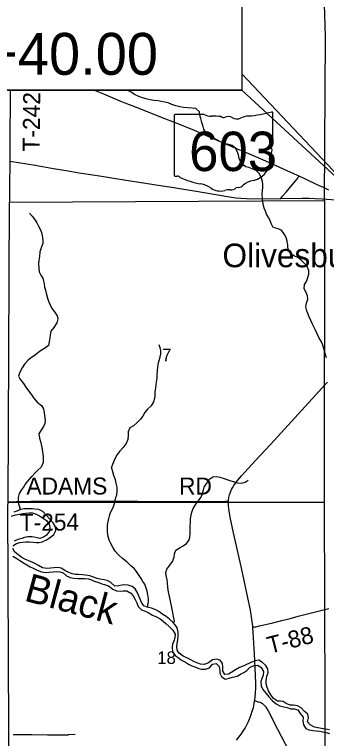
# Model space of a CAD drawing. Extents: x 0 to 34, y 0 to 22.
# Drawn here: x 5.455 to 6.497, y 15.494 to 17.915 of the extents above; entities that cross this region are included whole.
import ezdxf

# ---------------------------------------------------------------- set-up
doc = ezdxf.new("R2010")
doc.units = 0
for name, color, linetype in [('Default', 7, 'Continuous'), ('GM_X_County_Road', 7, 'Continuous'), ('GM_X_Major_River', 7, 'Continuous'), ('GM_X_Major_River_Text', 7, 'Continuous'), ('GM_X_Minor_River', 7, 'Continuous'), ('GM_X_Section', 7, 'Continuous'), ('GM_X_Section_Text', 7, 'Continuous'), ('GM_X_State_Location', 7, 'Continuous'), ('GM_X_State_Route', 7, 'Continuous'), ('GM_X_State_Shield', 7, 'Continuous'), ('GM_X_Township_Road', 7, 'Continuous'), ('GM_X_Township_Road_Text', 7, 'Continuous'), ('GM_X_Unincorporated_Text', 7, 'Continuous')]:
    doc.layers.add(name, color=color, linetype=linetype)

msp = doc.modelspace()

# ---------------------------------------------------------------- linework, layer by layer
at = {"layer": 'Default'}
for points in [[(4.3145, 18.3355), (4.3121, 18.3355), (4.3121, 17.6612), (6.2145, 17.6612), (6.2145, 17.662), (4.3145, 17.662)], [(6.2148, 17.662), (6.6166, 17.2903), (6.2148, 17.7158)]]:
    msp.add_lwpolyline(points, close=True, dxfattribs=at)
msp.add_lwpolyline([(6.2148, 18.2783), (6.2148, 17.662), (4.3145, 17.662), (4.3145, 18.28)], dxfattribs=at)
at = {"layer": 'GM_X_County_Road'}
msp.add_lwpolyline([(6.3846, 15.4277), (6.3348, 15.5244), (6.3034, 15.5851), (6.299, 15.5934), (6.2956, 15.5987), (6.2936, 15.6012), (6.2915, 15.6035), (6.2892, 15.6057), (6.2868, 15.6078), (6.2842, 15.6096), (6.2814, 15.6112), (6.2786, 15.6126), (6.2757, 15.6138), (6.2697, 15.6158), (6.2637, 15.6176), (6.2574, 15.6194)], dxfattribs=at)
at = {"layer": 'GM_X_Major_River'}
for points in [[(5.4447, 16.2375), (5.4588, 16.2412), (5.472, 16.2443), (5.4834, 16.2458), (5.4929, 16.2473), (5.5039, 16.2485), (5.5141, 16.2481), (5.5278, 16.2439), (5.5387, 16.2386), (5.549, 16.2322), (5.5622, 16.223), (5.571, 16.2105), (5.5736, 16.1995), (5.5717, 16.1866), (5.5618, 16.1737), (5.552, 16.1673), (5.5398, 16.1624), (5.5266, 16.1654), (5.5133, 16.168), (5.5, 16.1677), (5.489, 16.1654), (5.4796, 16.1631), (5.4663, 16.1589), (5.4542, 16.1536)], [(5.4496, 16.1385), (5.4617, 16.1457), (5.4731, 16.1491), (5.483, 16.1506), (5.4925, 16.151), (5.5053, 16.151), (5.5179, 16.1498), (5.5277, 16.1487), (5.5372, 16.1487), (5.5474, 16.1514), (5.5615, 16.1578), (5.5747, 16.1654), (5.5869, 16.176), (5.5937, 16.1893), (5.5922, 16.2014), (5.5842, 16.2151), (5.5736, 16.2268), (5.5619, 16.2394), (5.5497, 16.2526), (5.5361, 16.2598), (5.5232, 16.2606), (5.5137, 16.2614), (5.5005, 16.2621), (5.4857, 16.2617), (5.4758, 16.2591), (5.4626, 16.2541), (5.4527, 16.2503)], [(6.0438, 15.7566), (6.0332, 15.7626), (6.0181, 15.7695), (6.0048, 15.7789), (5.998, 15.7896), (5.9969, 15.8009), (5.998, 15.8112), (6.0003, 15.8237), (6.0022, 15.8362), (6.0022, 15.8495), (5.9984, 15.8635), (5.9923, 15.8734), (5.9836, 15.8832), (5.9734, 15.8927), (5.9616, 15.9014), (5.951, 15.9086), (5.937, 15.9185), (5.9272, 15.9238), (5.9124, 15.9295), (5.8984, 15.9333), (5.8877, 15.9371), (5.8794, 15.9481), (5.8749, 15.9598), (5.8696, 15.9727), (5.865, 15.9826), (5.8582, 15.9947), (5.848, 16.0019), (5.8343, 16.0069), (5.8237, 16.0073), (5.8139, 16.0061), (5.804, 16.0038), (5.7907, 16.0035), (5.7771, 16.0152), (5.7642, 16.0217), (5.7547, 16.0239), (5.7403, 16.027), (5.7308, 16.0292), (5.7161, 16.0342), (5.7062, 16.0372), (5.6918, 16.0399), (5.6823, 16.041), (5.6687, 16.0421), (5.6588, 16.0425), (5.6482, 16.0444), (5.6368, 16.049), (5.6236, 16.0558), (5.6107, 16.063), (5.6001, 16.0653), (5.5864, 16.0649), (5.5751, 16.0634), (5.5629, 16.0618), (5.5485, 16.0649), (5.5349, 16.0721), (5.5254, 16.0774), (5.5159, 16.0823), (5.5027, 16.088), (5.4898, 16.0933), (5.4792, 16.099), (5.4663, 16.1089), (5.4564, 16.1165), (5.4496, 16.1286)], [(5.4496, 16.1032), (5.4629, 16.0952), (5.4727, 16.0891), (5.4822, 16.0831), (5.4958, 16.074), (5.5076, 16.0679), (5.5174, 16.0634), (5.5311, 16.0569), (5.5455, 16.0508), (5.5587, 16.0486), (5.5713, 16.0497), (5.5841, 16.0516), (5.5963, 16.052), (5.6061, 16.0512), (5.6175, 16.0478), (5.6289, 16.0376), (5.641, 16.0319), (5.6535, 16.0296), (5.6664, 16.0289), (5.6804, 16.0289), (5.6899, 16.0292), (5.7028, 16.0273), (5.7123, 16.0239), (5.7217, 16.0198), (5.7335, 16.016), (5.7464, 16.011), (5.7562, 16.0084), (5.7695, 16.0042), (5.7831, 15.9928), (5.796, 15.9871), (5.8085, 15.9868), (5.818, 15.9879), (5.8305, 15.9875), (5.8438, 15.9803), (5.8517, 15.9708), (5.8582, 15.9587), (5.8635, 15.9473), (5.8684, 15.9348), (5.8798, 15.9242), (5.8919, 15.9193), (5.9018, 15.9151), (5.9158, 15.9067), (5.929, 15.9003), (5.9412, 15.8942), (5.9514, 15.8866), (5.9609, 15.8783), (5.9719, 15.8688), (5.984, 15.8555), (5.9916, 15.843), (5.9912, 15.8301), (5.987, 15.8195), (5.9832, 15.8089), (5.9813, 15.7994), (5.9824, 15.7839), (5.9919, 15.771), (6.0014, 15.7645), (6.0131, 15.7558), (6.026, 15.7486), (6.0359, 15.7429)], [(6.0359, 15.7429), (6.0457, 15.7383), (6.0579, 15.7338), (6.0704, 15.7277), (6.0802, 15.7251), (6.0935, 15.7255), (6.106, 15.7304), (6.1166, 15.7418), (6.1288, 15.7448), (6.139, 15.7349), (6.1409, 15.7217), (6.1416, 15.7122), (6.1466, 15.7012), (6.1587, 15.6921), (6.1727, 15.6959), (6.1837, 15.6985), (6.1985, 15.7019), (6.2106, 15.7088), (6.2209, 15.7145), (6.2311, 15.7213), (6.2429, 15.7327), (6.2554, 15.7384), (6.2683, 15.7395), (6.2793, 15.7315), (6.2868, 15.7175), (6.2857, 15.7039), (6.2815, 15.694), (6.2785, 15.683), (6.2792, 15.6701), (6.2849, 15.6572), (6.2959, 15.6443), (6.305, 15.6329), (6.316, 15.6212), (6.3292, 15.6102), (6.3414, 15.603), (6.3546, 15.5992), (6.3664, 15.5973), (6.3778, 15.5935), (6.3899, 15.5935), (6.402, 15.5897), (6.4092, 15.5779), (6.4191, 15.5647), (6.4187, 15.5521), (6.4206, 15.54), (6.4285, 15.5275), (6.438, 15.5229), (6.4513, 15.5207), (6.4634, 15.5199), (6.4736, 15.5184), (6.485, 15.5157), (6.4968, 15.5135), (6.507, 15.5108)], [(6.5074, 15.5229), (6.4937, 15.5252), (6.4812, 15.5275), (6.468, 15.5294), (6.4577, 15.532), (6.4433, 15.5392), (6.4342, 15.5499), (6.4376, 15.5628), (6.435, 15.5753), (6.4232, 15.5855), (6.413, 15.5965), (6.4001, 15.6033), (6.3876, 15.6056), (6.3755, 15.6056), (6.3622, 15.6106), (6.3528, 15.617), (6.3433, 15.6185), (6.3338, 15.6185), (6.3209, 15.6276), (6.3118, 15.6401), (6.3035, 15.6534), (6.2989, 15.664), (6.2963, 15.6765), (6.2963, 15.6864), (6.2986, 15.702), (6.302, 15.7133), (6.3016, 15.7266), (6.2933, 15.7391), (6.2838, 15.7475), (6.2717, 15.7558), (6.2588, 15.7532), (6.2467, 15.749), (6.2209, 15.7368), (6.2072, 15.7315), (6.1936, 15.7239), (6.1811, 15.7156), (6.1701, 15.7084), (6.1579, 15.7076), (6.1511, 15.7186), (6.1507, 15.733), (6.1496, 15.7444), (6.1424, 15.7562), (6.1295, 15.7588), (6.1163, 15.7566), (6.103, 15.7467), (6.0886, 15.741), (6.0768, 15.7425), (6.0643, 15.7471), (6.0541, 15.7516), (6.0438, 15.7566)]]:
    msp.add_lwpolyline(points, dxfattribs=at)
at = {"layer": 'GM_X_Minor_River'}
for points in [[(6.0807, 17.554), (6.0777, 17.5665), (6.0747, 17.5783), (6.0729, 17.5893), (6.0612, 17.6), (6.0483, 17.602), (6.0327, 17.6024), (6.0202, 17.604), (6.0073, 17.606), (5.9945, 17.6091), (5.9804, 17.6141), (5.9679, 17.6195), (5.9569, 17.6218), (5.9456, 17.6237), (5.935, 17.6257), (5.9221, 17.6273), (5.9088, 17.6296), (5.8982, 17.632), (5.8823, 17.6366), (5.8705, 17.6404), (5.8565, 17.647), (5.8467, 17.6535), (5.8361, 17.6592), (5.8273, 17.662)], [(6.4978, 16.7666), (6.4925, 16.781), (6.4895, 16.7932), (6.4851, 16.8088), (6.4802, 16.8202), (6.4723, 16.835), (6.4663, 16.8472), (6.461, 16.8594), (6.4554, 16.87), (6.4497, 16.8814), (6.4452, 16.8913), (6.4396, 16.9043), (6.4351, 16.9145), (6.4321, 16.924), (6.4288, 16.9373), (6.4307, 16.9491), (6.4346, 16.9631), (6.4335, 16.9741), (6.4294, 16.9852), (6.4233, 16.997), (6.4242, 17.0121), (6.4311, 17.022), (6.4341, 17.0322), (6.438, 17.047), (6.4384, 17.0591), (6.4324, 17.0717), (6.4222, 17.0843), (6.4128, 17.0938), (6.4015, 17.1022), (6.3901, 17.1065), (6.3791, 17.113), (6.372, 17.1248), (6.3686, 17.1343), (6.3679, 17.1438), (6.3661, 17.1567), (6.3627, 17.1688), (6.3571, 17.1795), (6.3469, 17.1936), (6.3325, 17.1997), (6.3192, 17.2028), (6.3125, 17.2158), (6.3087, 17.2264), (6.3034, 17.2359), (6.297, 17.247), (6.2937, 17.2572), (6.2896, 17.2675), (6.2869, 17.2774), (6.2847, 17.2888), (6.2832, 17.2987), (6.2829, 17.3139), (6.2838, 17.3264), (6.2842, 17.3359), (6.2842, 17.3461), (6.2831, 17.3568), (6.2794, 17.3712), (6.2726, 17.383), (6.2621, 17.3929), (6.2492, 17.3987), (6.2375, 17.4033), (6.228, 17.4056), (6.2129, 17.4159), (6.2061, 17.4331), (6.2031, 17.4452), (6.199, 17.4566), (6.1941, 17.4665), (6.1828, 17.4772), (6.1707, 17.4799), (6.16, 17.4819), (6.1434, 17.4892), (6.1328, 17.4941), (6.1203, 17.5014), (6.1059, 17.5091), (6.0953, 17.5182), (6.0874, 17.5312), (6.0852, 17.5407), (6.0807, 17.554)], [(5.5051, 17.2509), (5.5146, 17.2402), (5.5214, 17.2307), (5.5297, 17.2185), (5.5349, 17.2074), (5.5409, 17.1968), (5.5451, 17.1861), (5.5473, 17.1763), (5.5495, 17.1588), (5.5494, 17.1493), (5.5448, 17.1379), (5.5394, 17.1216), (5.5382, 17.1057), (5.5363, 17.092), (5.5355, 17.0818), (5.5358, 17.067), (5.5376, 17.0548), (5.5425, 17.0434), (5.5496, 17.0335), (5.5522, 17.0233), (5.5541, 17.0138), (5.5556, 17.0035), (5.5582, 16.9932), (5.5608, 16.9826), (5.5649, 16.9663), (5.5682, 16.9564), (5.5739, 16.9438), (5.5799, 16.9313), (5.5882, 16.9202), (5.5976, 16.9069), (5.5994, 16.897), (5.5967, 16.8837), (5.5864, 16.8686), (5.5765, 16.8557), (5.5741, 16.8428), (5.5726, 16.833), (5.5714, 16.8197), (5.5687, 16.8079), (5.5553, 16.7978), (5.5424, 16.7906), (5.531, 16.7816), (5.5207, 16.7736), (5.5089, 16.7653), (5.4994, 16.7582), (5.4883, 16.7457), (5.4807, 16.7328), (5.4734, 16.7188), (5.4684, 16.7059), (5.4733, 16.6961), (5.4853, 16.6812), (5.4933, 16.669), (5.5023, 16.6564), (5.5129, 16.642), (5.5189, 16.6324), (5.531, 16.6187), (5.5453, 16.6069), (5.5517, 16.5958), (5.5543, 16.5829), (5.5572, 16.5571), (5.5568, 16.5472), (5.5514, 16.5366), (5.5457, 16.5268), (5.5365, 16.5124), (5.5387, 16.4976), (5.5417, 16.4866), (5.5439, 16.4771), (5.5465, 16.4664), (5.5491, 16.4524), (5.551, 16.4372), (5.5513, 16.4265), (5.5505, 16.4171), (5.5438, 16.4013)], [(5.9375, 16.8115), (5.9401, 16.8016), (5.9423, 16.7913), (5.943, 16.7799), (5.9411, 16.7697), (5.938, 16.7602), (5.9346, 16.7504), (5.9326, 16.7363), (5.9318, 16.723), (5.9306, 16.7105), (5.9301, 16.6984), (5.9286, 16.6855), (5.9274, 16.676), (5.9258, 16.6654), (5.9242, 16.6529), (5.9238, 16.6411), (5.9226, 16.6312), (5.9195, 16.6191), (5.9119, 16.6062), (5.8997, 16.5953), (5.8905, 16.5843), (5.8836, 16.5718), (5.876, 16.5612), (5.8622, 16.548), (5.8527, 16.5397), (5.8405, 16.5326), (5.8352, 16.5197), (5.8347, 16.5079), (5.8335, 16.4939), (5.8282, 16.4802), (5.8186, 16.467), (5.8056, 16.4534), (5.798, 16.4432), (5.7923, 16.4333), (5.7869, 16.4216), (5.7827, 16.4102), (5.7796, 16.4008)], [(5.4742, 16.2585), (5.4736, 16.2644), (5.4698, 16.2773), (5.4679, 16.2871), (5.4679, 16.2993), (5.4721, 16.3133), (5.4781, 16.3239), (5.4846, 16.3334), (5.4907, 16.3433), (5.4994, 16.3547), (5.5127, 16.3702), (5.5225, 16.3812), (5.5324, 16.3899), (5.5438, 16.4013)], [(5.9006, 15.9327), (5.901, 15.9409), (5.9022, 15.9511), (5.9022, 15.9606), (5.9003, 15.9746), (5.8984, 15.9868), (5.8942, 16.0001), (5.8904, 16.0095), (5.884, 16.019), (5.8783, 16.0289), (5.8715, 16.0387), (5.8624, 16.052), (5.8544, 16.0619), (5.845, 16.0706), (5.831, 16.0835), (5.8154, 16.0956), (5.8029, 16.1074), (5.7912, 16.1207), (5.7843, 16.1309), (5.7768, 16.1457), (5.7711, 16.1575), (5.7677, 16.1696), (5.7658, 16.1832), (5.7654, 16.195), (5.7662, 16.2071), (5.7685, 16.2197), (5.77, 16.2291), (5.7723, 16.2386), (5.7757, 16.25), (5.781, 16.2595), (5.7863, 16.2701), (5.7894, 16.2796), (5.7916, 16.2898), (5.7939, 16.2993), (5.7966, 16.3088), (5.7981, 16.3209), (5.7977, 16.3346), (5.7947, 16.3475), (5.792, 16.3585), (5.7871, 16.3729), (5.7841, 16.3858), (5.7796, 16.4008)], [(5.9865, 15.88), (5.9893, 15.8863), (5.9867, 15.9022), (5.9844, 15.9147), (5.9821, 15.9257), (5.9791, 15.9371), (5.9772, 15.9477), (5.9749, 15.9591), (5.9727, 15.969), (5.9708, 15.9788), (5.9685, 15.9898), (5.9674, 15.9993), (5.9663, 16.0137), (5.9647, 16.0243), (5.9613, 16.0384), (5.961, 16.0486), (5.9636, 16.06), (5.9742, 16.0736), (5.9826, 16.0858), (5.9883, 16.0998), (5.9898, 16.1112), (5.9944, 16.1237), (6.008, 16.1321), (6.019, 16.1378), (6.0296, 16.1453), (6.0376, 16.1556), (6.0406, 16.1658), (6.0414, 16.1818), (6.0414, 16.195), (6.0422, 16.2056), (6.0426, 16.2151), (6.0429, 16.2261), (6.0437, 16.2356), (6.0475, 16.2504), (6.0521, 16.2633), (6.0604, 16.2773), (6.071, 16.291), (6.0782, 16.3005), (6.0832, 16.3126), (6.0862, 16.3248), (6.0885, 16.3346), (6.0976, 16.3475), (6.1044, 16.36), (6.1181, 16.3688), (6.131, 16.3695), (6.1408, 16.3672), (6.1552, 16.3631), (6.1647, 16.3597), (6.175, 16.3566), (6.189, 16.3525), (6.1992, 16.3487), (6.2121, 16.3471), (6.2257, 16.3506), (6.2352, 16.3574)]]:
    msp.add_lwpolyline(points, dxfattribs=at)
at = {"layer": 'GM_X_Section'}
for points in [[(5.4402, 17.662), (5.4379, 17.2873), (6.4911, 17.2929), (6.4945, 17.8409), (6.4805, 18.2714), (6.2148, 18.2748), (6.2148, 17.662)], [(5.4379, 17.2873), (6.4911, 17.2929), (6.4897, 16.2833), (5.4343, 16.2844)], [(5.4343, 16.2844), (6.4897, 16.2833), (6.4927, 15.2726), (5.4377, 15.2688), (5.4328, 16.2708)]]:
    msp.add_lwpolyline(points, close=True, dxfattribs=at)
at = {"layer": 'GM_X_State_Route'}
for points in [[(6.2082, 17.4615), (6.1586, 17.4824), (6.1045, 17.506), (6.056, 17.5267), (5.9986, 17.5504), (5.9465, 17.5708), (5.8712, 17.6), (5.8164, 17.6219), (5.7533, 17.6481), (5.7201, 17.662)], [(6.5049, 17.3275), (6.4937, 17.3328), (6.4848, 17.337), (6.4763, 17.3412), (6.4596, 17.3487), (6.406, 17.3741), (6.4006, 17.3766), (6.3411, 17.4033), (6.2844, 17.4288), (6.2302, 17.4522), (6.2082, 17.4615)], [(5.4404, 17.4242), (5.5242, 17.4104), (5.5855, 17.4001), (5.6346, 17.3919), (5.6714, 17.3858), (5.7389, 17.3751), (5.828, 17.3611), (5.8924, 17.3511), (5.9354, 17.3443), (5.9875, 17.3361), (6.0886, 17.319), (6.1805, 17.3036), (6.1959, 17.3016), (6.2113, 17.3002), (6.2299, 17.2993), (6.2546, 17.2989), (6.3446, 17.299), (6.4161, 17.3004), (6.4379, 17.3003), (6.4597, 17.2995), (6.4845, 17.2979), (6.5433, 17.2935)], [(6.2144, 16.0585), (6.209, 16.083), (6.1895, 16.171), (6.1768, 16.2286), (6.1732, 16.247), (6.1708, 16.2624), (6.1698, 16.2717), (6.1696, 16.2811), (6.1699, 16.2869), (6.1701, 16.2905), (6.1714, 16.2998), (6.1736, 16.3089), (6.1765, 16.3179), (6.1801, 16.3266), (6.1829, 16.3322), (6.1876, 16.3403), (6.193, 16.348), (6.2008, 16.3578), (6.2132, 16.3718), (6.2596, 16.422), (6.31, 16.4769), (6.4153, 16.5912), (6.4608, 16.6422), (6.4814, 16.6655), (6.492, 16.6769), (6.5008, 16.6856)], [(6.1969, 15.4884), (6.2047, 15.498), (6.2121, 15.5079), (6.219, 15.5182), (6.2254, 15.5288), (6.2313, 15.5397), (6.2366, 15.5508), (6.2414, 15.5622), (6.2457, 15.5738), (6.2496, 15.5856), (6.253, 15.5975), (6.2557, 15.6096), (6.2574, 15.6194), (6.2578, 15.6218), (6.2594, 15.6341), (6.2605, 15.6464), (6.2612, 15.6619), (6.2612, 15.6774), (6.2602, 15.7053), (6.2565, 15.7767), (6.2527, 15.8481), (6.2514, 15.8646), (6.2509, 15.8698), (6.2485, 15.8914), (6.2459, 15.9098), (6.2426, 15.9281), (6.2351, 15.9646), (6.2144, 16.0585)]]:
    msp.add_lwpolyline(points, dxfattribs=at)
at = {"layer": 'GM_X_State_Shield'}
for p, q in [((5.9889, 17.5772), (5.9889, 17.3771)), ((6.0887, 17.5806), (5.9921, 17.5806)), ((6.3185, 17.4809), (6.3185, 17.5856)), ((6.3185, 17.4809), (6.3185, 17.4809))]:
    msp.add_line(p, q, dxfattribs=at)
for centre, major_axis, start_param, end_param in [((5.9927, 17.5776), (0.00382, 0), 1.712693, 3.28349), ((6.1117, 17.6039), (0.037, 0), 4.042523, 4.731795), ((6.2011, 17.8535), (0.3495, 0), 4.814394, 5.042369), ((6.3148, 17.586), (0.00367, 0), 6.141152, 7.989035), ((6.1239, 17.4683), (0.133, 0), 1.404758, 1.657858), ((6.1541, 17.5786), (0.0107, 0), 3.836095, 5.185415), ((6.1698, 17.5555), (0.0222, 0), 0.950623, 2.079405), ((6.1985, 17.5872), (0.0267, 0), 4.081561, 5.145723), ((6.2457, 17.5195), (0.0703, 0), 1.699011, 2.107814), ((6.3146, 17.4805), (0.00393, 0), 5.05454, 6.418171), ((6.3176, 17.4732), (0.00568, 0), 1.883978, 3.671073), ((6.2815, 17.46), (0.0341, 0), 5.934695, 6.695948), ((6.2207, 17.4238), (0.0874, 0), 5.101752, 6.440018), ((6.3316, 17.4371), (0.0248, 0), 2.387724, 3.262537), ((5.9927, 17.3766), (0.00385, 0), 3.00124, 4.508301), ((5.9933, 17.3971), (0.0294, 0), 4.665946, 4.897461), ((5.9993, 17.3655), (0.0106, 0), 0.519207, 1.627899), ((6.1331, 17.5453), (0.2524, 0), 4.195997, 4.488961), ((6.0579, 17.2872), (0.079, 0), 0.823519, 1.323587), ((6.2001, 17.3302), (0.00752, 0), 1.147584, 2.315152), ((6.1969, 17.3577), (0.0282, 0), 4.937069, 5.64225), ((6.2575, 17.3209), (0.0479, 0), 1.647645, 2.488434), ((6.1433, 17.3645), (0.0501, 0), 4.026481, 4.996735), ((6.1723, 17.2953), (0.0412, 0), 1.495662, 1.94098), ((6.1759, 17.3495), (0.0267, 0), 4.691044, 5.507374)]:
    msp.add_ellipse(centre, major_axis=major_axis, ratio=0.8, start_param=start_param, end_param=end_param, dxfattribs=at)
at = {"layer": 'GM_X_Township_Road'}
for points in [[(6.3446, 17.299), (6.3476, 17.3027), (6.3508, 17.3068), (6.363, 17.3206), (6.378, 17.3391), (6.3961, 17.3607), (6.4016, 17.3679), (6.4033, 17.3703), (6.406, 17.3741)], [(5.4352, 16.2849), (5.4482, 16.2855), (5.4606, 16.2861), (5.5103, 16.2873), (5.5444, 16.2879), (5.6033, 16.288), (5.6934, 16.2876), (5.7462, 16.2876), (5.7927, 16.2872), (5.8672, 16.2871), (5.9324, 16.2865), (6.01, 16.2861), (6.0784, 16.2862), (6.159, 16.2869), (6.1699, 16.2869)], [(6.2514, 15.8646), (6.2582, 15.8667), (6.2612, 15.8675), (6.2731, 15.8708), (6.3185, 15.881), (6.3487, 15.8885), (6.3757, 15.8953), (6.4027, 15.9024), (6.4298, 15.9095), (6.5049, 15.9289)], [(5.4507, 15.5072), (5.4662, 15.5067), (5.5128, 15.5067), (5.5656, 15.506), (5.6026, 15.5063), (5.6088, 15.5063), (5.6249, 15.5062), (5.6339, 15.5066), (5.6354, 15.5068), (5.6364, 15.5071), (5.6574, 15.5084)]]:
    msp.add_lwpolyline(points, dxfattribs=at)

# ---------------------------------------------------------------- texts
at = {"layer": 'Default'}
msp.add_text('STA. 882+40.00', height=0.14, dxfattribs=at).set_placement((4.5763, 17.7131))
at = {"layer": 'GM_X_Major_River_Text'}
msp.add_text('Black', height=0.09473, rotation=344.8507, dxfattribs=at).set_placement((5.484, 15.9556))
at = {"layer": 'GM_X_Section_Text'}
for s, height, p in [('7', 0.0419, (5.9481, 16.7553)), ('18', 0.04186, (5.9319, 15.7432))]:
    msp.add_text(s, height=height, rotation=0, dxfattribs=at).set_placement(p)
at = {"layer": 'GM_X_State_Location'}
for s in ['s', 'r']:
    msp.add_text(s, height=0.000189, dxfattribs=at).set_placement((6.15, 17.4638))
msp.add_text('603', height=0.000189, rotation=0, dxfattribs=at).set_placement((6.0831, 17.45))
at = {"layer": 'GM_X_State_Shield'}
msp.add_text('603', height=0.13184, dxfattribs=at).set_placement((6.0384, 17.3912))
at = {"layer": 'GM_X_Township_Road_Text'}
for s, rotation, p in [('T-242', 89.4382, (5.5392, 17.4565)), ('ADAMS', 0.0007, (5.495, 16.3096)), ('RD', 0, (6.0048, 16.3096)), ('T-254', 0.545, (5.4727, 16.1878)), ('T-88', 14.2925, (6.3073, 15.7766))]:
    msp.add_text(s, height=0.05682, rotation=rotation, dxfattribs=at).set_placement(p)
at = {"layer": 'GM_X_Unincorporated_Text'}
msp.add_text('Olivesburg', height=0.07898, rotation=0, dxfattribs=at).set_placement((6.1498, 17.0697))

doc.saveas('drawing.dxf')
